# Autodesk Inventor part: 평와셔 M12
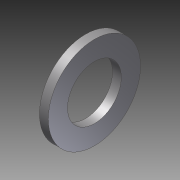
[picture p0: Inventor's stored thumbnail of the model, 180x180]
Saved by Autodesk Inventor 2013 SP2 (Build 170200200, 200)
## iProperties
Created: 2024-07
Part Number: 평와셔 M12
Material: Generic
Document SubType Name: Modeling
Designer: 601
Density: 1 g/cm^3
Author: 601
변환 표준: STEP AP214IS
전처리기: Build: 200, Release: 2013 SP2 Update 6 - Date: Thu 07/17/2014
전송 단위: 밀리미터
불확실성: 0.01
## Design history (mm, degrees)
node "평와셔 M121"
body "Solid1"
node "기준1"
